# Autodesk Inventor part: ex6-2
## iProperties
Shininess: 64.0
Length Units: 11272
Angle Units: 11279
Time Units: 11290
Mass Units: 11286
Length Display Precision: 3
Angle Display Precision: 2
Compacted: True
Part Number: ex6-2
Document SubType Name: Modeling
Created: 2002-11
Designer: Elise Moss
Density: 0.0
Volumn: 0.0
Area: 0.0
PropertySet Name: Model Information
Control State: 0
Master: False
Checked Out: False
Author: Elise Moss
